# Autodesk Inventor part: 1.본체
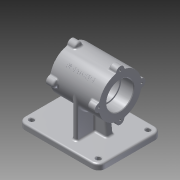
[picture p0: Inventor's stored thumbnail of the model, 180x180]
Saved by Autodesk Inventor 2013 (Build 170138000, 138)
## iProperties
Created: 2015-12
Part Number: 1.본체
Material: 알루미늄 6061
Document SubType Name: 판금
Designer: hana
Density: 2.40731 g/cm^3
Sheet Metal Rule: 기본값
Mass: 1036.86 g
Surface Area: 821.401 cm^2
Volume: 430.713 cm^3
Author: hana
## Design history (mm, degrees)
sketch "스케치1"
  geometry: L1 (-80, 55)-(60, 55); L2 (60, 55)-(60, -55); L3 (60, -55)-(-80, -55); L4 (-80, -55)-(-80, 55); 2 further points
  constraints: 8 end point, 2 parallel, 1 horizontal, 1 horizontal alignment, 1 midpoint, 1 perpendicular
  dimensions: "d0" = 140 distance of L1.start L1.end; "d2" = 110 distance of L3.end L1.start; "d3" = 80 distance from line of L4 point (0, 0)
extrude "돌출1" new body sketch "스케치1" distance "d4" = 10; taper "d5" = 0 deg
node "작업 평면1"
sketch "스케치2"
  geometry: L1 (-42.5, 117)-(42.5, 117); L2 (42.5, 117)-(42.5, 80); L3 (42.5, 80)-(-42.5, 80); L4 (-42.5, 80)-(-42.5, 117); L5 (-80, 0)-(-80, 10) reference; L6 (-80, 10)-(60, 10) reference; L7 (60, 10)-(60, 0) reference; L8 (60, 0)-(-80, 0) reference; 1 further point
  constraints: 8 end point, 2 perpendicular, 1 horizontal, 1 parallel
  dimensions: "d7" = 74 diameter of L1 L3; "d9" = 85 distance of L1.start L1.end; "d10" = 37.5 distance between parallel lines of L4 L5; "d11" = 80 distance from line of L8 L3.end
revolve "회전1" sketch "스케치2" stored, may be unused: angle "d12" = 90 deg
sketch "스케치3"
  geometry: L1 (-80, 0)-(-80, 10) reference; L2 (-80, 10)-(60, 10) reference; L3 (60, 10)-(60, 0) reference; L4 (60, 0)-(-80, 0) reference; L5 (-42.5, 43)-(-42.5, 117) reference; L6 (-42.5, 117)-(42.5, 117) reference; L7 (42.5, 117)-(42.5, 43) reference; L8 (42.5, 43)-(-42.5, 43) reference; L9 (-42.5, 80)-(42.5, 80); L10 (42.5, 103.5)-(20.5, 103.5); L11 (20.5, 103.5)-(20.5, 101); L12 (20.5, 101)-(-20.5, 101); L13 (-20.5, 101)-(-20.5, 103.5); L14 (-20.5, 103.5)-(-42.5, 103.5); L15 (-42.5, 103.5)-(-42.5, 80); L16 (42.5, 103.5)-(42.5, 80); 1 further point
  constraints: 16 end point, 3 parallel, 3 perpendicular, 2 midpoint, 2 point on line, 1 collinear
  dimensions: "d13" = 47 diameter of L14 L9; "d15" = 47 diameter of L10 L9; "d16" = 42 diameter of L12 L9; "d17" = 22 distance of L13.end L14.end; "d18" = 41 distance of L11.end L12.end
revolve "회전2" sketch "스케치3" stored, may be unused: angle "d19" = 90 deg
sketch "스케치4"
  geometry: C1 r 23.5 at (0, 0) reference; C2 r 7 at (-37, 0); C3 r 7 at (0, 37); C4 r 7 at (37, 0); C5 r 7 at (0, -37); 1 further point
  constraints: 4 centre point, 2 horizontal alignment, 2 vertical alignment
  dimensions: "d20" = 37 distance of C1.centre C2.centre; "d21" = 14 diameter of C2; "d22" = 14 diameter of C3; "d23" = 14 diameter of C4; "d24" = 14 diameter of C5; "d25" = 37 distance of C3.centre C1.centre; "d26" = 37 distance of C4.centre C1.centre; "d27" = 37 distance of C1.centre C5.centre
extrude "돌출2" join sketch "스케치4" distance "d28" = 15; taper "d29" = 0 deg
sketch "스케치5"
  geometry: A1 r 7 centre (0, 0) between (-0.662, -6.969) and (-0.662, 6.969) reference; A2 r 7 centre (-37, 37) between (-30.031, 36.338) and (-43.969, 36.338) reference; A3 r 7 centre (-74, 0) between (-73.338, 6.969) and (-73.338, -6.969) reference; A4 r 7 centre (-37, -37) between (-43.969, -36.338) and (-30.031, -36.338) reference; 1 further point
hole "구멍1" sketch "스케치5" at (-74, 0), (-37, -37), (0, 0), (-37, 37) diameter "d30" = 3.242; stored, may be unused: countersink angle "d34" = 90 deg, drill point angle "d36" = 118 deg; dims "d31" = 9, "d32" = 4, "d33" = 2, "d35" = 11
node "작업 평면2"
sketch "스케치6"
  geometry: L1 (-4, 37)-(4, 37); L2 (4, 37)-(4, -37); L3 (4, -37)-(-4, -37); L4 (-4, -37)-(-4, 37); 3 further points
  constraints: 8 end point, 2 midpoint, 2 parallel, 1 horizontal, 1 horizontal alignment, 1 perpendicular, 1 vertical alignment
  dimensions: "d37" = 8 distance of L1.start L1.end; "d39" = 74 distance of L3.end L1.start
extrude "돌출3" join sketch "스케치6" stored distance "d40" = 15; taper "d41" = 0 deg
sketch "스케치7"
  geometry: L1 (42.5, 103.5)-(20.5, 103.5) reference; L2 (20.5, 103.5)-(20.5, 101) reference; L3 (20.5, 101)-(-20.5, 101) reference; L4 (-20.5, 101)-(-20.5, 103.5) reference; L5 (-20.5, 103.5)-(-42.5, 103.5) reference; L6 (-42.5, 103.5)-(-42.5, 115.379) reference; L7 (-42.5, 115.379)-(-31.5, 115.379) reference; L8 (-31.5, 115.379)-(-30.526, 117) reference; L9 (-30.526, 117)-(-31.5, 118.621) reference; L10 (-31.5, 118.621)-(-42.5, 118.621) reference; L11 (-42.5, 118.621)-(-42.5, 124) reference; L12 (-42.5, 124)-(-27.5, 124) reference; L13 (-27.5, 124)-(-27.5, 117) reference; L14 (-27.5, 117)-(27.5, 117) reference; L15 (27.5, 117)-(27.5, 124) reference; L16 (27.5, 124)-(42.5, 124) reference; L17 (42.5, 124)-(42.5, 118.621) reference; L18 (42.5, 118.621)-(31.5, 118.621) reference; L19 (31.5, 118.621)-(30.526, 117) reference; L20 (30.526, 117)-(31.5, 115.379) reference; L21 (31.5, 115.379)-(42.5, 115.379) reference; L22 (42.5, 115.379)-(42.5, 103.5) reference; L23 (-80, 0)-(-80, 10) reference; L24 (-80, 10)-(-4, 10) reference; L25 (-4, 10)-(-4, 43) reference; L26 (-4, 43)-(-27.5, 43) reference; L27 (-27.5, 43)-(-27.5, 36) reference; L28 (-27.5, 36)-(-42.5, 36) reference; L29 (-42.5, 36)-(-42.5, 41.379) reference; L30 (-42.5, 41.379)-(-31.5, 41.379) reference; L31 (-31.5, 41.379)-(-30.526, 43) reference; L32 (-30.526, 43)-(-31.5, 44.621) reference; L33 (-31.5, 44.621)-(-42.5, 44.621) reference; L34 (-42.5, 44.621)-(-42.5, 56.5) reference; L35 (-42.5, 56.5)-(-20.5, 56.5) reference; L36 (-20.5, 56.5)-(-20.5, 59) reference; L37 (-20.5, 59)-(20.5, 59) reference; L38 (20.5, 59)-(20.5, 56.5) reference; L39 (20.5, 56.5)-(42.5, 56.5) reference; L40 (42.5, 56.5)-(42.5, 44.621) reference; L41 (42.5, 44.621)-(31.5, 44.621) reference; L42 (31.5, 44.621)-(30.526, 43) reference; L43 (30.526, 43)-(31.5, 41.379) reference; L44 (31.5, 41.379)-(42.5, 41.379) reference; L45 (42.5, 41.379)-(42.5, 36) reference; L46 (42.5, 36)-(27.5, 36) reference; L47 (27.5, 36)-(27.5, 43) reference; L48 (27.5, 43)-(4, 43) reference; L49 (4, 43)-(4, 10) reference; L50 (4, 10)-(60, 10) reference; L51 (60, 10)-(60, 0) reference; L52 (60, 0)-(-80, 0) reference; L53 (-20.948, 43)-(-25, 10); L54 (20.948, 43)-(25, 10); 1 further point
  constraints: 4 end point, 4 point on line
  dimensions: "d42" = 97 deg angle of L53 L24; "d44" = 25 horizontal distance of point (0, 0) L53.end; "d45" = 25 horizontal distance of L54.end point (0, 0); "d46" = 97 deg angle of L50 L54
  node "절단 모서리 투영3"
feature "리브1" dims "d47" = 1, "d48" = 12, "d49" = 0, "d50" = 0, "d51" = 1, "d52" = 1
feature "리브2" dims "d53" = 1, "d54" = 12, "d55" = 0, "d56" = 0, "d57" = 1, "d58" = 1
sketch "스케치8"
  geometry: L1 (80, -55)-(80, 55) reference; L2 (80, 55)-(-60, 55) reference; L3 (-60, 55)-(-60, -55) reference; L4 (-60, -55)-(80, -55) reference; C1 r 4 at (-48, 43); C2 r 4 at (68, 43); C3 r 4 at (68, -43); C4 r 4 at (-48, -43); 1 further point
  constraints: 4 centre point
  dimensions: "d59" = 8 diameter of C1; "d61" = 8 diameter of C2; "d62" = 8 diameter of C3; "d63" = 8 diameter of C4; "d64" = 12 distance from line of L3 C1.centre; "d65" = 12 distance from line of L2 C1.centre; "d66" = 12 distance from line of L4 C4.centre; "d67" = 12 distance from line of L3 C4.centre; "d68" = 12 distance from line of L1 C3.centre; "d69" = 12 distance from line of L4 C3.centre; "d70" = 12 distance from line of L2 C2.centre; "d71" = 12 distance from line of L1 C2.centre
extrude "돌출4" cut sketch "스케치8" stored distance "d72" = 15; taper "d73" = 0 deg
fillet "모깎기1" dims "d74" = 12
fillet "모깎기2" dims "d75" = 3
fillet "모깎기3" dims "d76" = 3
fillet "모깎기4" dims "d77" = 3
chamfer "모따기1" distance "d78" = 1; stored, may be unused: second distance "d79" = 2, angle "d80" = 45 deg
fillet "모깎기5" dims "d81" = 0.3
node "작업 평면5"
  node "작업 평면4"
node "작업 평면7"
  node "작업 평면6"
sketch "스케치12"
  geometry: L1 (-42.5, 0)-(42.5, 0) reference; L2 (-42.5, 30.622)-(-42.5, 37) reference; 3 further points
  constraints: 1 coincident, 1 midpoint, 1 other
  dimensions: "d87" = 42.5 distance from line of point (0, 0) L2
feature "엠보싱2" sketch "스케치12" dims "d88" = 0.5, "d89" = 0
chamfer "모따기2" distance "d90" = 1; stored, may be unused: second distance "d91" = 2, angle "d92" = 45 deg
chamfer "모따기3" distance "d93" = 7; stored, may be unused: second distance "d94" = 2, angle "d95" = 20 deg
fillet "모깎기6" dims "d96" = 3
fillet "모깎기7" dims "d97" = 3
fillet "모깎기8" dims "d98" = 3
chamfer "모따기4" distance "d99" = 7; stored, may be unused: second distance "d100" = 2, angle "d101" = 20 deg
chamfer "모따기5" distance "d102" = 7; stored, may be unused: second distance "d103" = 2, angle "d104" = 20 deg
chamfer "모따기6" distance "d105" = 7; stored, may be unused: second distance "d106" = 2, angle "d107" = 20 deg
chamfer "모따기7" distance "d108" = 7; stored, may be unused: second distance "d109" = 2, angle "d110" = 20 deg
chamfer "모따기8" distance "d111" = 7; stored, may be unused: second distance "d112" = 2, angle "d113" = 20 deg
chamfer "모따기9" distance "d114" = 7; stored, may be unused: second distance "d115" = 2, angle "d116" = 20 deg
chamfer "모따기10" distance "d117" = 7; stored, may be unused: second distance "d118" = 2, angle "d119" = 20 deg
fillet "모깎기9" dims "d120" = 3
fillet "모깎기10" dims "d121" = 3
fillet "모깎기11" dims "d122" = 3
node "솔리드1"
mirror "대칭1"
node "작업 평면3"
node "작업축1"
node "작업축2"
node "절단 모서리 투영1"
node "절단 모서리 투영2"
node "절단 모서리 투영6"
other parameters: "d6" = 90 deg, "d82" = -45 deg, "d86" = 45 deg, "K계수" = 4.4, "BendRadius" = 0.5 (derived), "BendReliefWidth" = 0.5 (derived), "BendReliefDepth" = 0.25 (derived), "CornerReliefSize" = 2 (derived), "SeamGap" = 0.01, "MinimumRemnant" = 1 (derived), "TransitionRadius" = 0.5 (= BendRadius)
